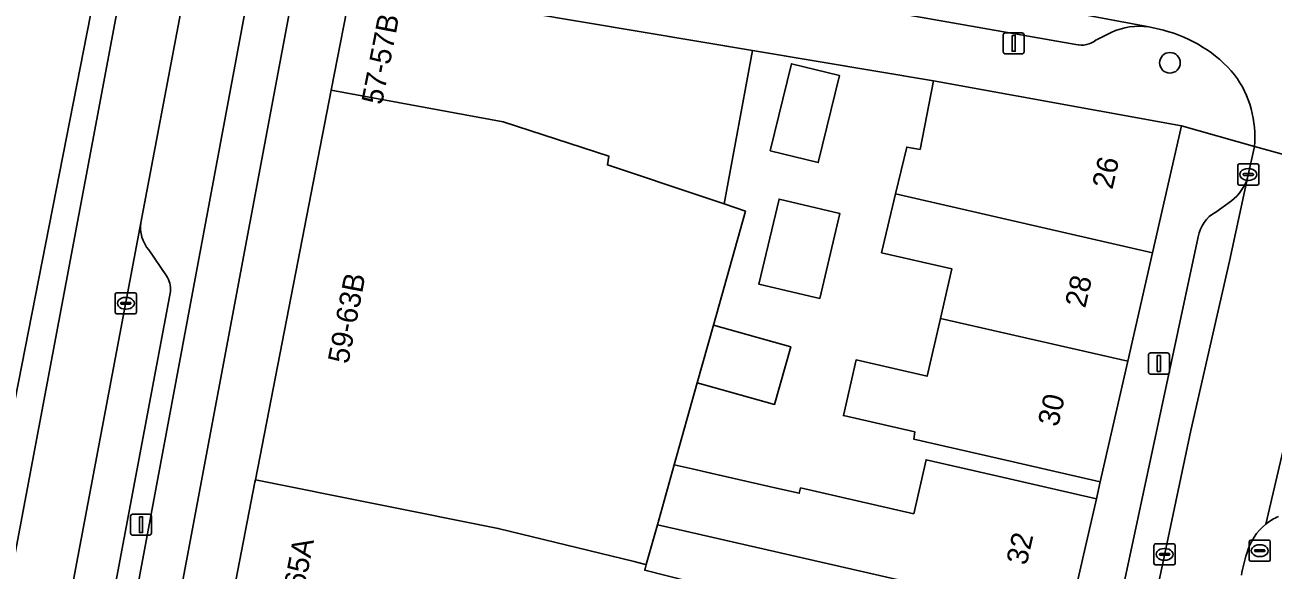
# Model space of a CAD drawing. Extents: x 161838 to 162344, y 381620 to 382160.
# Drawn here: x 161893.7 to 161952.9, y 381906.3 to 381932.1 of the extents above; entities that cross this region are included whole.
import ezdxf

# ---------------------------------------------------------------- set-up
doc = ezdxf.new("R2010")
doc.units = 0
for name, color, linetype in [('IMGEO_Berm_open', 7, 'Continuous'), ('IMGEO_Boom', 7, 'Continuous'), ('IMGEO_Erf', 7, 'Continuous'), ('IMGEO_Fietspad_gesloten', 7, 'Continuous'), ('IMGEO_Kolk', 7, 'Continuous'), ('IMGEO_Lichtmast', 7, 'Continuous'), ('IMGEO_Muur', 7, 'Continuous'), ('IMGEO_OVBaan_gesloten', 7, 'Continuous'), ('IMGEO_Pand', 7, 'Continuous'), ('IMGEO_Pand_nummerreeks', 7, 'Continuous'), ('IMGEO_Parkeervlak_open', 7, 'Continuous'), ('IMGEO_Rijbaan_lokaal_gesloten', 7, 'Continuous'), ('IMGEO_Rijbaan_lokaal_open', 7, 'Continuous'), ('IMGEO_Voetpad_open', 7, 'Continuous')]:
    doc.layers.add(name, color=color, linetype=linetype)

msp = doc.modelspace()

# ---------------------------------------------------------------- linework, layer by layer
at = {"layer": 'IMGEO_Berm_open'}
for points in [[(161897.858, 381899.101), (161916.698, 382000), (161921.558, 382026.031), (161926.346, 382051.921)], [(161905.11, 381954.479), (161905.076, 381954.299), (161904.686, 381952.125), (161903.787, 381947.27), (161902.001, 381937.624), (161901.082, 381932.662), (161899.202, 381922.742)], [(161899.588, 381921.451), (161900.429, 381920.223)], [(161900.616, 381919.482), (161896.821, 381899.305), (161895.517, 381892.371), (161895.218, 381891.646), (161894.941, 381890.914)]]:
    msp.add_lwpolyline(points, dxfattribs=at)
for centre, radius, start, end in [((161900.859, 381922.534), 1.67, 172.85869, 220.4339), ((161899.475, 381919.588), 1.146, 354.67877, 33.64828)]:
    msp.add_arc(centre, radius, start, end, dxfattribs=at)
at = {"layer": 'IMGEO_Boom'}
msp.add_circle((161947.987, 381930.325), 0.489, dxfattribs=at)
at = {"layer": 'IMGEO_Erf'}
for points in [[(161937.644, 381920.56), (161934.322, 381921.32), (161934.983, 381924.105), (161935.509, 381926.324), (161936.143, 381926.218), (161936.778, 381929.475), (161928.197, 381930.913), (161926.864, 381923.63), (161927.867, 381923.294), (161926.351, 381917.885), (161930.013, 381916.858), (161929.247, 381914.125), (161925.585, 381915.152), (161924.496, 381911.265), (161925.342, 381911.071), (161926.228, 381910.869), (161929.201, 381910.189), (161930.421, 381909.91), (161930.48, 381910.168), (161935.847, 381908.941), (161936.433, 381911.503), (161939.631, 381910.771), (161944.505, 381909.656), (161944.68, 381910.458), (161939.806, 381911.573), (161935.856, 381912.476), (161935.9, 381912.824), (161932.51, 381913.6), (161933.113, 381916.235), (161936.478, 381915.465), (161937.106, 381918.207)], [(161929.033, 381926.156), (161930.043, 381930.28), (161932.331, 381929.72), (161931.321, 381925.595)], [(161931.393, 381919.142), (161928.504, 381919.826), (161929.458, 381923.859), (161932.348, 381923.176)], [(161938.282, 381904.875), (161935.138, 381905.596), (161935.128, 381905.808), (161924.684, 381908.197), (161923.699, 381908.422), (161923.168, 381906.529), (161923.093, 381906.261), (161926.341, 381905.451), (161925.851, 381903.561), (161928.875, 381902.898), (161934.252, 381901.719), (161934.773, 381904.315), (161938.005, 381903.624), (161942.903, 381902.621), (161943.156, 381903.76)]]:
    msp.add_lwpolyline(points, close=True, dxfattribs=at)
at = {"layer": 'IMGEO_Fietspad_gesloten'}
for points in [[(161897.095, 381883.929), (161899.866, 381898.705), (161907.39, 381938.834), (161908.427, 381944.469), (161918.786, 382000), (161923.625, 382025.943), (161928.95, 382054.459)], [(161926.346, 382051.921), (161921.558, 382026.031), (161916.698, 382000), (161897.858, 381899.101), (161895.081, 381884.229), (161870.207, 381751.91), (161869.854, 381750), (161864.774, 381722.548), (161862.987, 381712.892), (161857.316, 381682.246)]]:
    msp.add_lwpolyline(points, dxfattribs=at)
at = {"layer": 'IMGEO_Kolk'}
for p, q in [((161951.277, 381925.527), (161952.129, 381925.527)), ((161951.202, 381924.601), (161951.202, 381925.453)), ((161951.461, 381925.021), (161951.461, 381925.033)), ((161951.899, 381924.984), (161951.501, 381924.984)), ((161951.504, 381925.07), (161951.902, 381925.07)), ((161951.69, 381925.307), (161951.715, 381925.307)), ((161951.945, 381925.033), (161951.945, 381925.021)), ((161952.203, 381925.453), (161952.203, 381924.601)), ((161952.129, 381924.527), (161951.277, 381924.527)), ((161951.713, 381924.747), (161951.688, 381924.747)), ((161897.999, 381918.495), (161897.999, 381919.347)), ((161898.074, 381919.421), (161898.926, 381919.421)), ((161898.487, 381919.201), (161898.512, 381919.201)), ((161899, 381919.347), (161899, 381918.495)), ((161898.926, 381918.421), (161898.074, 381918.421)), ((161898.258, 381918.915), (161898.258, 381918.927)), ((161898.696, 381918.878), (161898.298, 381918.878)), ((161898.301, 381918.964), (161898.699, 381918.964)), ((161898.51, 381918.641), (161898.485, 381918.641)), ((161898.742, 381918.927), (161898.742, 381918.915)), ((161947.232, 381906.589), (161947.232, 381907.441)), ((161947.307, 381907.515), (161948.159, 381907.515)), ((161947.72, 381907.295), (161947.745, 381907.295)), ((161948.233, 381907.441), (161948.233, 381906.589)), ((161951.745, 381906.764), (161951.745, 381907.616)), ((161951.82, 381907.69), (161952.672, 381907.69)), ((161952.004, 381907.184), (161952.004, 381907.196)), ((161952.047, 381907.233), (161952.445, 381907.233)), ((161952.233, 381907.47), (161952.258, 381907.47)), ((161952.488, 381907.196), (161952.488, 381907.184)), ((161952.746, 381907.616), (161952.746, 381906.764)), ((161947.491, 381907.009), (161947.491, 381907.021)), ((161947.929, 381906.972), (161947.531, 381906.972)), ((161947.534, 381907.058), (161947.932, 381907.058)), ((161947.743, 381906.735), (161947.718, 381906.735)), ((161947.975, 381907.021), (161947.975, 381907.009)), ((161952.672, 381906.69), (161951.82, 381906.69)), ((161952.442, 381907.147), (161952.044, 381907.147)), ((161952.256, 381906.91), (161952.231, 381906.91)), ((161948.159, 381906.515), (161947.307, 381906.515))]:
    msp.add_line(p, q, dxfattribs=at)
for points in [[(161951.277, 381925.527), (161952.129, 381925.527)], [(161951.202, 381924.601), (161951.202, 381925.453)], [(161952.203, 381925.453), (161952.203, 381924.601)], [(161952.129, 381924.527), (161951.277, 381924.527)], [(161897.999, 381918.495), (161897.999, 381919.347)], [(161898.074, 381919.421), (161898.926, 381919.421)], [(161899, 381919.347), (161899, 381918.495)], [(161898.926, 381918.421), (161898.074, 381918.421)], [(161947.232, 381906.589), (161947.232, 381907.441)], [(161947.307, 381907.515), (161948.159, 381907.515)], [(161948.233, 381907.441), (161948.233, 381906.589)], [(161951.745, 381906.764), (161951.745, 381907.616)], [(161951.82, 381907.69), (161952.672, 381907.69)], [(161952.746, 381907.616), (161952.746, 381906.764)], [(161952.672, 381906.69), (161951.82, 381906.69)], [(161948.159, 381906.515), (161947.307, 381906.515)]]:
    msp.add_lwpolyline(points, dxfattribs=at)
for centre, radius, start, end in [((161951.279, 381925.451), 0.0765, 91.55205, 178.44795), ((161951.279, 381925.451), 0.0765, 91.55205, 178.44795), ((161952.127, 381925.451), 0.0765, 1.55205, 88.44795), ((161952.127, 381925.451), 0.0765, 1.55205, 88.44795), ((161951.501, 381925.03), 0.0403, 85.87752, 175.75265), ((161951.498, 381925.02), 0.0366, 178.93798, 274.71019), ((161951.902, 381925.027), 0.043, 264.86636, 352.45326), ((161951.906, 381925.032), 0.0386, 1.73085, 96.63898), ((161951.279, 381924.603), 0.0765, 181.55205, 268.44795), ((161951.279, 381924.603), 0.0765, 181.55205, 268.44795), ((161952.127, 381924.603), 0.0765, 271.55205, 358.44795), ((161952.127, 381924.603), 0.0765, 271.55205, 358.44795), ((161898.076, 381919.345), 0.0765, 91.55205, 178.44795), ((161898.076, 381919.345), 0.0765, 91.55205, 178.44795), ((161898.924, 381919.345), 0.0765, 1.55205, 88.44795), ((161898.924, 381919.345), 0.0765, 1.55205, 88.44795), ((161898.076, 381918.497), 0.0765, 181.55205, 268.44795), ((161898.076, 381918.497), 0.0765, 181.55205, 268.44795), ((161898.298, 381918.924), 0.0403, 85.87752, 175.75265), ((161898.295, 381918.914), 0.0366, 178.93798, 274.71019), ((161898.699, 381918.921), 0.043, 264.86636, 352.45326), ((161898.703, 381918.926), 0.0386, 1.73085, 96.63898), ((161898.924, 381918.497), 0.0765, 271.55205, 358.44795), ((161898.924, 381918.497), 0.0765, 271.55205, 358.44795), ((161947.309, 381907.439), 0.0765, 91.55205, 178.44795), ((161947.309, 381907.439), 0.0765, 91.55205, 178.44795), ((161948.157, 381907.439), 0.0765, 1.55205, 88.44795), ((161948.157, 381907.439), 0.0765, 1.55205, 88.44795), ((161951.822, 381907.614), 0.0765, 91.55205, 178.44795), ((161951.822, 381907.614), 0.0765, 91.55205, 178.44795), ((161952.044, 381907.193), 0.0403, 85.87752, 175.75265), ((161952.041, 381907.183), 0.0366, 178.93798, 274.71019), ((161952.445, 381907.19), 0.043, 264.86636, 352.45326), ((161952.449, 381907.195), 0.0386, 1.73085, 96.63898), ((161952.67, 381907.614), 0.0765, 1.55205, 88.44795), ((161952.67, 381907.614), 0.0765, 1.55205, 88.44795), ((161947.309, 381906.591), 0.0765, 181.55205, 268.44795), ((161947.309, 381906.591), 0.0765, 181.55205, 268.44795), ((161947.531, 381907.018), 0.0403, 85.87752, 175.75265), ((161947.528, 381907.008), 0.0366, 178.93798, 274.71019), ((161947.932, 381907.015), 0.043, 264.86636, 352.45326), ((161947.936, 381907.02), 0.0386, 1.73085, 96.63898), ((161948.157, 381906.591), 0.0765, 271.55205, 358.44795), ((161948.157, 381906.591), 0.0765, 271.55205, 358.44795), ((161951.822, 381906.766), 0.0765, 181.55205, 268.44795), ((161951.822, 381906.766), 0.0765, 181.55205, 268.44795), ((161952.67, 381906.766), 0.0765, 271.55205, 358.44795), ((161952.67, 381906.766), 0.0765, 271.55205, 358.44795)]:
    msp.add_arc(centre, radius, start, end, dxfattribs=at)
for centre, major_axis, ratio, start_param, end_param in [((161951.689, 381925.027), (-0.387, 0.002), 0.722429, 4.712389, 7.853982), ((161951.714, 381925.027), (-0.39, 0.002), 0.717154, 1.570796, 4.712389), ((161898.486, 381918.921), (-0.387, 0.002), 0.722429, 4.712389, 7.853982), ((161898.511, 381918.921), (-0.39, 0.002), 0.717154, 1.570796, 4.712389), ((161947.719, 381907.015), (-0.387, 0.002), 0.722429, 4.712389, 7.853982), ((161947.744, 381907.015), (-0.39, 0.002), 0.717154, 1.570796, 4.712389), ((161952.232, 381907.19), (-0.387, 0.002), 0.722429, 4.712389, 7.853982), ((161952.257, 381907.19), (-0.39, 0.002), 0.717154, 1.570796, 4.712389)]:
    msp.add_ellipse(centre, major_axis=major_axis, ratio=ratio, start_param=start_param, end_param=end_param, dxfattribs=at)
at = {"layer": 'IMGEO_Lichtmast'}
for p, q in [((161940.083, 381930.844), (161940.083, 381931.644)), ((161940.083, 381931.644), (161940.083, 381930.844)), ((161940.183, 381931.744), (161940.973, 381931.744)), ((161940.973, 381931.744), (161940.183, 381931.744)), ((161941.073, 381931.644), (161941.073, 381930.844)), ((161941.073, 381930.844), (161941.073, 381931.644)), ((161940.973, 381930.744), (161940.183, 381930.744)), ((161940.183, 381930.744), (161940.973, 381930.744)), ((161946.97, 381915.666), (161946.97, 381916.466)), ((161946.97, 381916.466), (161946.97, 381915.666)), ((161947.07, 381916.566), (161947.86, 381916.566)), ((161947.86, 381916.566), (161947.07, 381916.566)), ((161947.96, 381916.466), (161947.96, 381915.666)), ((161947.96, 381915.666), (161947.96, 381916.466)), ((161947.86, 381915.566), (161947.07, 381915.566)), ((161947.07, 381915.566), (161947.86, 381915.566)), ((161898.72, 381908.021), (161898.72, 381908.821)), ((161898.72, 381908.821), (161898.72, 381908.021)), ((161898.82, 381908.921), (161899.61, 381908.921)), ((161899.61, 381908.921), (161898.82, 381908.921)), ((161899.71, 381908.821), (161899.71, 381908.021)), ((161899.71, 381908.021), (161899.71, 381908.821)), ((161899.61, 381907.921), (161898.82, 381907.921)), ((161898.82, 381907.921), (161899.61, 381907.921))]:
    msp.add_line(p, q, dxfattribs=at)
for points in [[(161940.503, 381931.619), (161940.653, 381931.619), (161940.653, 381930.869), (161940.503, 381930.869), (161940.503, 381931.619)], [(161947.39, 381916.441), (161947.54, 381916.441), (161947.54, 381915.691), (161947.39, 381915.691), (161947.39, 381916.441)], [(161899.14, 381908.796), (161899.29, 381908.796), (161899.29, 381908.046), (161899.14, 381908.046), (161899.14, 381908.796)]]:
    msp.add_lwpolyline(points, dxfattribs=at)
for centre, start, end in [((161940.183, 381931.644), 90, 180), ((161940.183, 381931.644), 90, 180), ((161940.973, 381931.644), 0, 90), ((161940.973, 381931.644), 360, 90), ((161940.183, 381930.844), 180, 270), ((161940.183, 381930.844), 180, 270), ((161940.973, 381930.844), 270, 0), ((161940.973, 381930.844), 270, 0), ((161947.07, 381916.466), 90, 180), ((161947.07, 381916.466), 90, 180), ((161947.86, 381916.466), 0, 90), ((161947.86, 381916.466), 360, 90), ((161947.07, 381915.666), 180, 270), ((161947.07, 381915.666), 180, 270), ((161947.86, 381915.666), 270, 0), ((161947.86, 381915.666), 270, 0), ((161898.82, 381908.821), 90, 180), ((161898.82, 381908.821), 90, 180), ((161899.61, 381908.821), 0, 90), ((161899.61, 381908.821), 360, 90), ((161898.82, 381908.021), 180, 270), ((161898.82, 381908.021), 180, 270), ((161899.61, 381908.021), 270, 0), ((161899.61, 381908.021), 270, 0)]:
    msp.add_arc(centre, 0.1, start, end, dxfattribs=at)
at = {"layer": 'IMGEO_Muur'}
msp.add_lwpolyline([(161936.778, 381929.475), (161917.463, 381932.711)], dxfattribs=at)
at = {"layer": 'IMGEO_OVBaan_gesloten'}
msp.add_lwpolyline([(161858.651, 381720.96), (161859.425, 381726.158), (161861.132, 381736.231), (161869.606, 381781.344), (161897.211, 381928.16), (161915.531, 382025.949), (161915.767, 382027.092), (161920.812, 382054.098), (161923.657, 382069.694), (161925.944, 382081.248), (161931.886, 382108.929), (161933.831, 382119.131), (161934.302, 382121.796), (161934.443, 382123.117), (161933.101, 382124.399), (161916.93, 382035.129), (161911.481, 382007.357), (161883.773, 381866.122), (161869.795, 381786.79), (161847.814, 381679.325), (161847.327, 381677.629)], dxfattribs=at)
at = {"layer": 'IMGEO_Pand'}
for points in [[(161928.197, 381930.913), (161917.463, 381932.711), (161909.938, 381934.153), (161909.255, 381934.284), (161908.231, 381929.021), (161916.384, 381927.527), (161921.399, 381925.893), (161921.324, 381925.485), (161925.907, 381923.95), (161926.864, 381923.63)], [(161929.033, 381926.156), (161931.321, 381925.595), (161932.331, 381929.72), (161930.043, 381930.28)], [(161934.983, 381924.105), (161947.165, 381921.319), (161948.542, 381927.34), (161936.778, 381929.475), (161936.143, 381926.218), (161935.509, 381926.324)], [(161921.399, 381925.893), (161916.384, 381927.527), (161908.231, 381929.021), (161904.636, 381910.55), (161916.152, 381908.245), (161922.591, 381906.67), (161923.069, 381906.553), (161923.168, 381906.529), (161923.699, 381908.422), (161924.496, 381911.265), (161925.585, 381915.152), (161926.351, 381917.885), (161927.867, 381923.294), (161926.864, 381923.63), (161925.907, 381923.95), (161921.324, 381925.485)], [(161931.393, 381919.142), (161932.348, 381923.176), (161929.458, 381923.859), (161928.504, 381919.826)], [(161934.983, 381924.105), (161934.322, 381921.32), (161937.644, 381920.56), (161937.106, 381918.207), (161945.988, 381916.176), (161947.165, 381921.319)], [(161926.351, 381917.885), (161925.585, 381915.152), (161929.247, 381914.125), (161930.013, 381916.858)], [(161937.106, 381918.207), (161936.478, 381915.465), (161933.113, 381916.235), (161932.51, 381913.6), (161935.9, 381912.824), (161935.856, 381912.476), (161939.806, 381911.573), (161944.68, 381910.458), (161945.988, 381916.176)], [(161944.505, 381909.656), (161939.631, 381910.771), (161936.433, 381911.503), (161935.847, 381908.941), (161930.48, 381910.168), (161930.421, 381909.91), (161929.201, 381910.189), (161926.228, 381910.869), (161925.342, 381911.071), (161924.496, 381911.265), (161923.699, 381908.422), (161924.684, 381908.197), (161935.128, 381905.808), (161935.138, 381905.596), (161938.282, 381904.875), (161943.156, 381903.76)], [(161923.168, 381906.529), (161923.069, 381906.553), (161922.591, 381906.67), (161916.152, 381908.245), (161904.636, 381910.55), (161904.615, 381910.446), (161903.341, 381903.897), (161905.201, 381903.534), (161905.299, 381904.038), (161909.961, 381903.128), (161909.687, 381901.727), (161917.356, 381900.23), (161922.583, 381899.012), (161921.374, 381894.671), (161923.437, 381894.255), (161924.39, 381897.931), (161925.021, 381900.361), (161925.851, 381903.561), (161926.341, 381905.451), (161923.093, 381906.261)]]:
    msp.add_lwpolyline(points, close=True, dxfattribs=at)
at = {"layer": 'IMGEO_Parkeervlak_open'}
for points in [[(161946.986, 381932.028), (161922.495, 381936.626)], [(161917.959, 381935.664), (161924.459, 381934.562), (161943.52, 381931.198)], [(161944.499, 381931.406), (161945.2, 381931.768)], [(161944.759, 381892.73), (161946.476, 381901.072), (161948.977, 381912.889), (161950.814, 381920.923), (161951.669, 381924.865)], [(161950.91, 381923.775), (161950.157, 381923.248)], [(161956.15, 381923.966), (161955.529, 381921.276), (161952.539, 381908.452)], [(161899.202, 381922.742), (161894.868, 381899.69), (161871.456, 381775.156)], [(161949.322, 381922.074), (161942.677, 381890.978), (161942.053, 381887.623), (161941.701, 381885.647), (161941.088, 381882.227)], [(161900.429, 381920.223), (161899.588, 381921.451)], [(161894.941, 381890.914), (161895.218, 381891.646), (161895.517, 381892.371), (161896.821, 381899.305), (161900.616, 381919.482)]]:
    msp.add_lwpolyline(points, dxfattribs=at)
for centre, radius, start, end in [((161946.545, 381928.796), 3.262, 82.22104, 114.34446), ((161943.802, 381932.277), 1.115, 255.33771, 308.65189), ((161949.526, 381925.548), 2.249, 307.97672, 342.32195), ((161951.006, 381921.76), 1.713, 119.70537, 169.45044), ((161900.859, 381922.534), 1.67, 172.85869, 220.4339), ((161899.475, 381919.588), 1.146, 354.67877, 33.64828), ((161954.236, 381906.355), 2.698, 114.1858, 128.98599)]:
    msp.add_arc(centre, radius, start, end, dxfattribs=at)
at = {"layer": 'IMGEO_Rijbaan_lokaal_gesloten'}
for points in [[(161918.789, 382041.718), (161915.767, 382027.092), (161915.531, 382025.949), (161897.211, 381928.16), (161869.606, 381781.344), (161861.132, 381736.231), (161859.425, 381726.158), (161858.651, 381720.96)], [(161862.533, 381727.211), (161866.175, 381746.944), (161866.739, 381750), (161866.904, 381750.735), (161870.759, 381771.481), (161871.456, 381775.156), (161894.868, 381899.69), (161899.202, 381922.742), (161901.082, 381932.662), (161902.001, 381937.624), (161903.787, 381947.27), (161904.686, 381952.125), (161905.076, 381954.299), (161905.11, 381954.479), (161913.622, 382000), (161917.608, 382021.312), (161917.651, 382021.542), (161920.351, 382034.502), (161920.367, 382034.753)]]:
    msp.add_lwpolyline(points, dxfattribs=at)
at = {"layer": 'IMGEO_Rijbaan_lokaal_open'}
for points in [[(161956.934, 381934.662), (161956.559, 381934.761), (161948.397, 381936.525), (161945.23, 381937.136), (161936.936, 381938.606), (161936.675, 381938.652), (161932.946, 381939.313), (161932.48, 381939.395), (161923.265, 381941.028), (161922.495, 381936.626), (161946.986, 381932.028), (161947.69, 381931.869)], [(161956.425, 381925.136), (161951.992, 381926.357), (161951.669, 381924.865), (161950.814, 381920.923), (161948.977, 381912.889), (161946.476, 381901.072), (161944.759, 381892.73)], [(161951.992, 381926.357), (161956.425, 381925.136), (161956.663, 381925.423)], [(161952.539, 381908.452), (161955.529, 381921.276)]]:
    msp.add_lwpolyline(points, dxfattribs=at)
for centre, radius, start, end in [((161946.055, 381925.531), 6.545, 40.17783, 75.5364), ((161947.096, 381926.836), 4.919, 354.41712, 36.39261), ((161954.243, 381906.342), 2.712, 128.93257, 164.56816), ((161960.593, 381904.324), 9.373, 163.00559, 169.52188)]:
    msp.add_arc(centre, radius, start, end, dxfattribs=at)
at = {"layer": 'IMGEO_Voetpad_open'}
for points in [[(161907.39, 381938.834), (161899.866, 381898.705), (161897.095, 381883.929), (161872.236, 381751.615), (161871.936, 381750), (161866.402, 381720.165)], [(161901.744, 381895.676), (161902.239, 381898.237), (161902.268, 381898.386), (161903.341, 381903.897), (161904.615, 381910.446), (161904.636, 381910.55), (161908.231, 381929.021), (161909.255, 381934.284), (161909.938, 381934.153), (161910.655, 381938.724), (161910.232, 381938.9), (161910.088, 381938.932)], [(161915.76, 381937.772), (161915.69, 381937.784), (161910.655, 381938.724), (161909.938, 381934.153), (161917.463, 381932.711), (161928.197, 381930.913), (161936.778, 381929.475), (161948.542, 381927.34), (161951.992, 381926.357)], [(161943.52, 381931.198), (161924.459, 381934.562), (161917.959, 381935.664)], [(161947.69, 381931.869), (161946.986, 381932.028)], [(161945.2, 381931.768), (161944.499, 381931.406)], [(161951.669, 381924.865), (161951.992, 381926.357), (161948.542, 381927.34), (161947.165, 381921.319), (161945.988, 381916.176), (161944.68, 381910.458), (161944.505, 381909.656), (161943.156, 381903.76), (161942.903, 381902.621), (161941.739, 381896.935), (161940.574, 381891.248), (161940.073, 381888.9), (161939.482, 381884.734), (161938.852, 381880.284), (161937.91, 381873.639), (161937.059, 381867.638), (161936.898, 381865.542), (161936.376, 381858.707), (161935.934, 381852.933)], [(161950.157, 381923.248), (161950.91, 381923.775)], [(161941.088, 381882.227), (161941.701, 381885.647), (161942.053, 381887.623), (161941.562, 381887.714), (161942.186, 381891.069), (161942.677, 381890.978), (161949.322, 381922.074)]]:
    msp.add_lwpolyline(points, dxfattribs=at)
for centre, radius, start, end in [((161946.545, 381928.796), 3.262, 82.22104, 114.34446), ((161946.055, 381925.531), 6.545, 40.17783, 75.5364), ((161943.802, 381932.277), 1.115, 255.33771, 308.65189), ((161947.096, 381926.836), 4.919, 354.41712, 36.39261), ((161949.526, 381925.548), 2.249, 307.97672, 342.32195), ((161951.006, 381921.76), 1.713, 119.70537, 169.45044), ((161954.243, 381906.342), 2.712, 128.93257, 164.56816), ((161954.236, 381906.355), 2.698, 114.1858, 128.98599), ((161960.593, 381904.324), 9.373, 163.00559, 169.52188)]:
    msp.add_arc(centre, radius, start, end, dxfattribs=at)

# ---------------------------------------------------------------- texts
at = {"layer": 'IMGEO_Pand_nummerreeks'}
for s, rotation, p in [('57-57B', 78.98796, (161910.638, 381928.298)), ('26', 77.11449, (161945.258, 381924.283)), ('59-63B', 78.98796, (161909.041, 381916.011)), ('28', 77.11449, (161943.971, 381918.659)), ('30', 77.11449, (161942.684, 381913.031)), ('32', 77.11439, (161941.19, 381906.462)), ('65-65A', 78.98796, (161906.596, 381903.448))]:
    msp.add_text(s, height=1, rotation=rotation, dxfattribs=at).set_placement(p)

doc.saveas('drawing.dxf')
